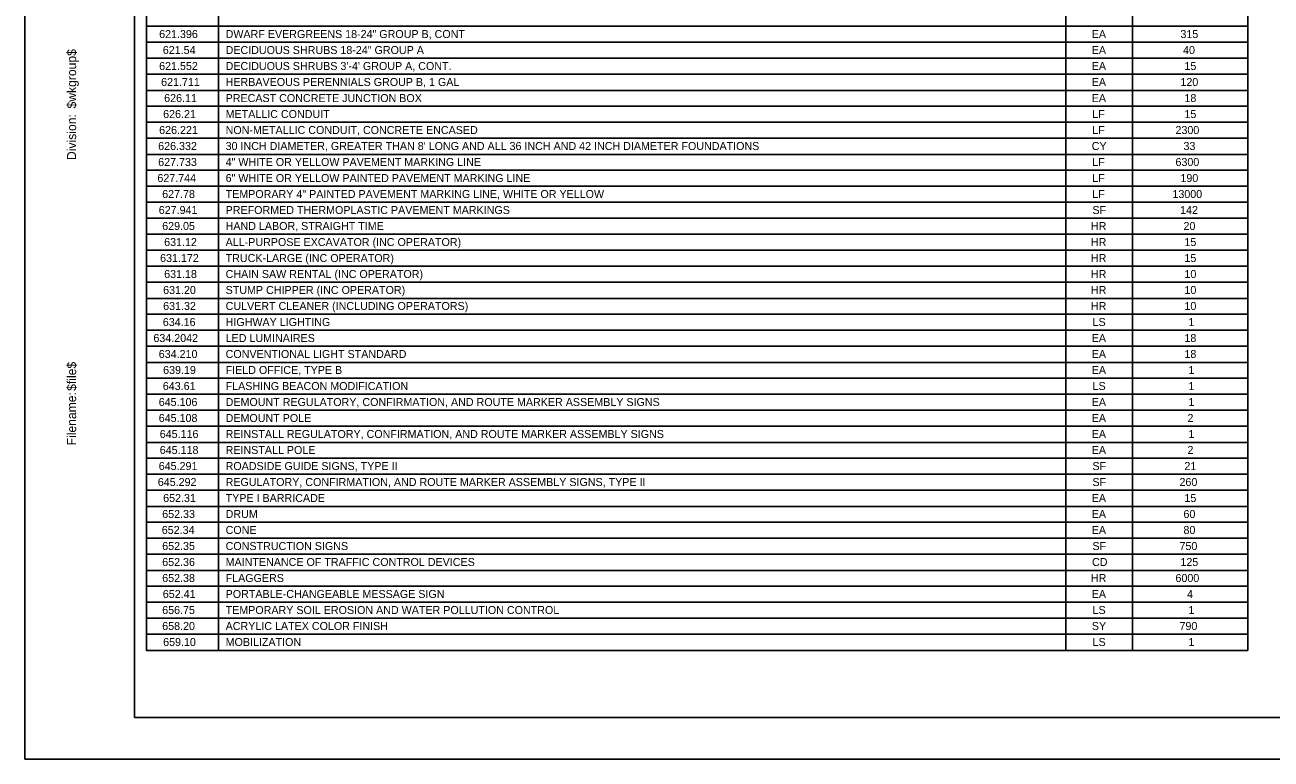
# Model space of a CAD drawing. Extents: x 2075518.1 to 2075585.6, y 1172412.5 to 1172434.5.
# Drawn here: x 2075518.14 to 2075536.53, y 1172412.49 to 1172423.33 of the extents above; entities that cross this region are included whole.
import ezdxf

# ---------------------------------------------------------------- set-up
doc = ezdxf.new("R2010")
doc.units = 0
doc.layers.add('Border', color=7, linetype='Continuous')
doc.layers.add('PLOT BOUNDARY', color=7, linetype='Continuous')

msp = doc.modelspace()

# ---------------------------------------------------------------- linework, layer by layer
at = {"layer": 'Border'}
for p, q in [((2075519.755, 1172434.098), (2075519.755, 1172413.098)), ((2075533.496, 1172433.936), (2075533.496, 1172414.092)), ((2075534.481, 1172433.936), (2075534.481, 1172414.092)), ((2075520.993, 1172432.994), (2075520.993, 1172414.092)), ((2075519.93, 1172423.305), (2075536.182, 1172423.305)), ((2075519.93, 1172423.069), (2075536.182, 1172423.069)), ((2075519.93, 1172422.833), (2075536.182, 1172422.833)), ((2075519.93, 1172422.597), (2075536.182, 1172422.597)), ((2075519.93, 1172422.36), (2075536.182, 1172422.36)), ((2075519.93, 1172422.124), (2075536.182, 1172422.124)), ((2075519.93, 1172421.888), (2075536.182, 1172421.888)), ((2075519.93, 1172421.652), (2075536.182, 1172421.652)), ((2075519.93, 1172421.415), (2075536.182, 1172421.415)), ((2075519.93, 1172421.179), (2075536.182, 1172421.179)), ((2075519.93, 1172420.943), (2075536.182, 1172420.943)), ((2075519.93, 1172420.707), (2075536.182, 1172420.707)), ((2075519.93, 1172420.471), (2075536.182, 1172420.471)), ((2075519.93, 1172420.234), (2075536.182, 1172420.234)), ((2075519.93, 1172419.998), (2075536.182, 1172419.998)), ((2075519.93, 1172419.762), (2075536.182, 1172419.762)), ((2075519.93, 1172419.526), (2075536.182, 1172419.526)), ((2075519.93, 1172419.289), (2075536.182, 1172419.289)), ((2075519.93, 1172419.053), (2075536.182, 1172419.053)), ((2075519.93, 1172418.817), (2075536.182, 1172418.817)), ((2075519.93, 1172418.581), (2075536.182, 1172418.581)), ((2075519.93, 1172418.344), (2075536.182, 1172418.344)), ((2075519.93, 1172418.108), (2075536.182, 1172418.108)), ((2075519.93, 1172417.872), (2075536.182, 1172417.872)), ((2075519.93, 1172417.636), (2075536.182, 1172417.636)), ((2075519.93, 1172417.4), (2075536.182, 1172417.4)), ((2075519.93, 1172417.163), (2075536.182, 1172417.163)), ((2075519.93, 1172416.927), (2075536.182, 1172416.927)), ((2075519.93, 1172416.691), (2075536.182, 1172416.691)), ((2075519.93, 1172416.455), (2075536.182, 1172416.455)), ((2075519.93, 1172416.218), (2075536.182, 1172416.218)), ((2075519.93, 1172415.982), (2075536.182, 1172415.982)), ((2075519.93, 1172415.746), (2075536.182, 1172415.746)), ((2075519.93, 1172415.51), (2075536.182, 1172415.51)), ((2075519.93, 1172415.273), (2075536.182, 1172415.273)), ((2075519.93, 1172415.037), (2075536.182, 1172415.037)), ((2075519.93, 1172414.801), (2075536.182, 1172414.801)), ((2075519.93, 1172414.565), (2075536.182, 1172414.565)), ((2075519.93, 1172414.329), (2075536.182, 1172414.329)), ((2075519.755, 1172413.098), (2075551.755, 1172413.098))]:
    msp.add_line(p, q, dxfattribs=at)
msp.add_lwpolyline([(2075536.182, 1172414.092), (2075519.93, 1172414.092), (2075519.93, 1172433.936), (2075536.182, 1172433.936), (2075536.182, 1172414.092)], dxfattribs=at)
at = {"layer": 'PLOT BOUNDARY'}
msp.add_lwpolyline([(2075518.136, 1172412.486), (2075552.136, 1172412.486), (2075552.136, 1172434.486), (2075518.136, 1172434.486)], close=True, dxfattribs=at)

# ---------------------------------------------------------------- texts
at = {"layer": 'Border'}
for s, height, p in [('621.396', 0.1181, (2075520.117, 1172423.132)), ('DWARF EVERGREENS 18-24" GROUP B, CONT', 0.11811, (2075521.098, 1172423.132)), ('EA', 0.1181, (2075533.879, 1172423.132)), ('315', 0.1181, (2075535.188, 1172423.132)), ('621.54', 0.1181, (2075520.171, 1172422.896)), ('DECIDUOUS SHRUBS 18-24" GROUP A', 0.11811, (2075521.098, 1172422.896)), ('EA', 0.1181, (2075533.879, 1172422.896)), ('40', 0.1181, (2075535.227, 1172422.896)), ('621.552', 0.1181, (2075520.117, 1172422.66)), ("DECIDUOUS SHRUBS 3'-4' GROUP A, CONT.", 0.11811, (2075521.098, 1172422.66)), ('EA', 0.1181, (2075533.879, 1172422.66)), ('15', 0.1181, (2075535.247, 1172422.66)), ('621.711', 0.1181, (2075520.146, 1172422.424)), ('HERBAVEOUS PERENNIALS GROUP B, 1 GAL', 0.11811, (2075521.098, 1172422.424)), ('EA', 0.1181, (2075533.879, 1172422.424)), ('120', 0.1181, (2075535.188, 1172422.424)), ('626.11', 0.1181, (2075520.191, 1172422.187)), ('PRECAST CONCRETE JUNCTION BOX', 0.11811, (2075521.098, 1172422.187)), ('EA', 0.1181, (2075533.879, 1172422.187)), ('18', 0.1181, (2075535.247, 1172422.187)), ('626.21', 0.1181, (2075520.176, 1172421.951)), ('METALLIC CONDUIT', 0.11811, (2075521.098, 1172421.951)), ('LF', 0.1181, (2075533.887, 1172421.951)), ('15', 0.1181, (2075535.247, 1172421.951)), ('626.221', 0.1181, (2075520.117, 1172421.715)), ('NON-METALLIC CONDUIT, CONCRETE ENCASED', 0.11811, (2075521.098, 1172421.715)), ('LF', 0.1181, (2075533.887, 1172421.715)), ('2300', 0.1181, (2075535.115, 1172421.715)), ('626.332', 0.1181, (2075520.103, 1172421.479)), ("30 INCH DIAMETER, GREATER THAN 8' LONG AND ALL 36 INCH AND 42 INCH DIAMETER FOUNDATIONS", 0.11811, (2075521.098, 1172421.479)), ('CY', 0.1181, (2075533.879, 1172421.479)), ('33', 0.1181, (2075535.233, 1172421.479)), ('627.733', 0.1181, (2075520.103, 1172421.243)), ('4" WHITE OR YELLOW PAVEMENT MARKING LINE', 0.11811, (2075521.098, 1172421.243)), ('LF', 0.1181, (2075533.887, 1172421.243)), ('6300', 0.1181, (2075535.115, 1172421.243)), ('627.744', 0.1181, (2075520.091, 1172421.006)), ('6" WHITE OR YELLOW PAINTED PAVEMENT MARKING LINE', 0.11811, (2075521.098, 1172421.006)), ('LF', 0.1181, (2075533.887, 1172421.006)), ('190', 0.1181, (2075535.188, 1172421.006)), ('627.78', 0.1181, (2075520.162, 1172420.77)), ('TEMPORARY 4" PAINTED PAVEMENT MARKING LINE, WHITE OR YELLOW', 0.11811, (2075521.098, 1172420.77)), ('LF', 0.1181, (2075533.887, 1172420.77)), ('13000', 0.1181, (2075535.07, 1172420.77)), ('627.941', 0.1181, (2075520.111, 1172420.534)), ('PREFORMED THERMOPLASTIC PAVEMENT MARKINGS', 0.11811, (2075521.098, 1172420.534)), ('SF', 0.1181, (2075533.89, 1172420.534)), ('142', 0.1181, (2075535.183, 1172420.534)), ('629.05', 0.1181, (2075520.162, 1172420.298)), ('HAND LABOR, STRAIGHT TIME                     ', 0.11811, (2075521.098, 1172420.298)), ('HR                ', 0.11811, (2075533.867, 1172420.298)), ('20', 0.1181, (2075535.233, 1172420.298)), ('631.12', 0.1181, (2075520.191, 1172420.061)), ('ALL-PURPOSE EXCAVATOR (INC OPERATOR)                ', 0.11811, (2075521.098, 1172420.061)), ('HR                ', 0.11811, (2075533.867, 1172420.061)), ('15', 0.1181, (2075535.247, 1172420.061)), ('631.172', 0.1181, (2075520.131, 1172419.825)), ('TRUCK-LARGE (INC OPERATOR)                    ', 0.11811, (2075521.098, 1172419.825)), ('HR                ', 0.11811, (2075533.867, 1172419.825)), ('15', 0.1181, (2075535.247, 1172419.825)), ('631.18', 0.1181, (2075520.191, 1172419.589)), ('CHAIN SAW RENTAL (INC OPERATOR)', 0.11811, (2075521.098, 1172419.589)), ('HR                ', 0.11811, (2075533.867, 1172419.589)), ('10', 0.1181, (2075535.247, 1172419.589)), ('631.20', 0.1181, (2075520.176, 1172419.353)), ('STUMP CHIPPER (INC OPERATOR)', 0.11811, (2075521.098, 1172419.353)), ('HR                ', 0.11811, (2075533.867, 1172419.353)), ('10', 0.1181, (2075535.247, 1172419.353)), ('631.32', 0.1181, (2075520.176, 1172419.117)), ('CULVERT CLEANER (INCLUDING OPERATORS)', 0.11811, (2075521.098, 1172419.117)), ('HR                ', 0.11811, (2075533.867, 1172419.117)), ('10', 0.1181, (2075535.247, 1172419.117)), ('634.16', 0.1181, (2075520.171, 1172418.88)), ('HIGHWAY LIGHTING', 0.11811, (2075521.098, 1172418.88)), ('LS', 0.1181, (2075533.892, 1172418.88)), ('1', 0.118, (2075535.306, 1172418.88)), ('634.2042', 0.1181, (2075520.032, 1172418.644)), ('LED LUMINAIRES', 0.11811, (2075521.098, 1172418.644)), ('EA', 0.1181, (2075533.879, 1172418.644)), ('18', 0.1181, (2075535.247, 1172418.644)), ('634.210', 0.1181, (2075520.111, 1172418.408)), ('CONVENTIONAL LIGHT STANDARD', 0.11811, (2075521.098, 1172418.408)), ('EA', 0.1181, (2075533.879, 1172418.408)), ('18', 0.1181, (2075535.247, 1172418.408)), ('639.19', 0.1181, (2075520.176, 1172418.172)), ('FIELD OFFICE, TYPE B', 0.11811, (2075521.098, 1172418.172)), ('EA', 0.1181, (2075533.879, 1172418.172)), ('1', 0.118, (2075535.306, 1172418.172)), ('643.61', 0.1181, (2075520.171, 1172417.935)), ('FLASHING BEACON MODIFICATION', 0.11811, (2075521.098, 1172417.935)), ('LS', 0.1181, (2075533.892, 1172417.935)), ('1', 0.118, (2075535.306, 1172417.935)), ('645.106', 0.1181, (2075520.111, 1172417.699)), ('DEMOUNT REGULATORY, CONFIRMATION, AND ROUTE MARKER ASSEMBLY SIGNS', 0.11811, (2075521.098, 1172417.699)), ('EA', 0.1181, (2075533.879, 1172417.699)), ('1', 0.118, (2075535.306, 1172417.699)), ('645.108', 0.1181, (2075520.111, 1172417.463)), ('DEMOUNT POLE', 0.11811, (2075521.098, 1172417.463)), ('EA', 0.1181, (2075533.879, 1172417.463)), ('2', 0.118, (2075535.292, 1172417.463)), ('645.116', 0.1181, (2075520.126, 1172417.227)), ('REINSTALL REGULATORY, CONFIRMATION, AND ROUTE MARKER ASSEMBLY SIGNS', 0.11811, (2075521.098, 1172417.227)), ('EA', 0.1181, (2075533.879, 1172417.227)), ('1', 0.118, (2075535.306, 1172417.227)), ('645.118', 0.1181, (2075520.126, 1172416.991)), ('REINSTALL POLE', 0.11811, (2075521.098, 1172416.991)), ('EA', 0.1181, (2075533.879, 1172416.991)), ('2', 0.118, (2075535.292, 1172416.991)), ('645.291', 0.1181, (2075520.111, 1172416.754)), ('ROADSIDE GUIDE SIGNS, TYPE II', 0.11811, (2075521.098, 1172416.754)), ('SF', 0.1181, (2075533.89, 1172416.754)), ('21', 0.1181, (2075535.247, 1172416.754)), ('645.292', 0.1181, (2075520.097, 1172416.518)), ('REGULATORY, CONFIRMATION, AND ROUTE MARKER ASSEMBLY SIGNS, TYPE II', 0.11811, (2075521.098, 1172416.518)), ('SF', 0.1181, (2075533.89, 1172416.518)), ('260', 0.1181, (2075535.174, 1172416.518)), ('652.31', 0.1181, (2075520.176, 1172416.282)), ('TYPE I BARRICADE', 0.11811, (2075521.098, 1172416.282)), ('EA', 0.1181, (2075533.879, 1172416.282)), ('15', 0.1181, (2075535.247, 1172416.282)), ('652.33', 0.1181, (2075520.162, 1172416.046)), ('DRUM', 0.1181, (2075521.098, 1172416.046)), ('EA', 0.1181, (2075533.879, 1172416.046)), ('60', 0.1181, (2075535.233, 1172416.046)), ('652.34', 0.1181, (2075520.156, 1172415.81)), ('CONE', 0.1181, (2075521.098, 1172415.81)), ('EA', 0.1181, (2075533.879, 1172415.81)), ('80', 0.1181, (2075535.233, 1172415.81)), ('652.35', 0.1181, (2075520.162, 1172415.573)), ('CONSTRUCTION SIGNS', 0.11811, (2075521.098, 1172415.573)), ('SF', 0.1181, (2075533.89, 1172415.573)), ('750', 0.1181, (2075535.174, 1172415.573)), ('652.36', 0.1181, (2075520.162, 1172415.337)), ('MAINTENANCE OF TRAFFIC CONTROL DEVICES', 0.11811, (2075521.098, 1172415.337)), ('CD', 0.1181, (2075533.884, 1172415.337)), ('125', 0.1181, (2075535.188, 1172415.337)), ('652.38', 0.1181, (2075520.162, 1172415.101)), ('FLAGGERS', 0.1181, (2075521.098, 1172415.101)), ('HR', 0.1181, (2075533.867, 1172415.101)), ('6000', 0.1181, (2075535.115, 1172415.101)), ('652.41', 0.1181, (2075520.171, 1172414.865)), ('PORTABLE-CHANGEABLE MESSAGE SIGN', 0.11811, (2075521.098, 1172414.865)), ('EA', 0.1181, (2075533.879, 1172414.865)), ('4', 0.118, (2075535.286, 1172414.865)), ('656.75', 0.1181, (2075520.162, 1172414.628)), ('TEMPORARY SOIL EROSION AND WATER POLLUTION CONTROL', 0.11811, (2075521.098, 1172414.628)), ('LS', 0.1181, (2075533.892, 1172414.628)), ('1', 0.118, (2075535.306, 1172414.628)), ('658.20', 0.1181, (2075520.162, 1172414.392)), ('ACRYLIC LATEX COLOR FINISH', 0.11811, (2075521.098, 1172414.392)), ('SY', 0.1181, (2075533.881, 1172414.392)), ('790', 0.1181, (2075535.174, 1172414.392)), ('659.10', 0.1181, (2075520.176, 1172414.156)), ('MOBILIZATION', 0.11811, (2075521.098, 1172414.156)), ('LS', 0.1181, (2075533.892, 1172414.156)), ('1', 0.118, (2075535.306, 1172414.156))]:
    msp.add_text(s, height=height, dxfattribs=at).set_placement(p)
for s, p in [('$wkgroup$', (2075518.892, 1172422.092)), ('Division:', (2075518.892, 1172421.331)), ('$file$', (2075518.892, 1172417.923)), ('Filename:', (2075518.892, 1172417.118))]:
    msp.add_text(s, height=0.1339, rotation=90, dxfattribs=at).set_placement(p)

doc.saveas('drawing.dxf')
